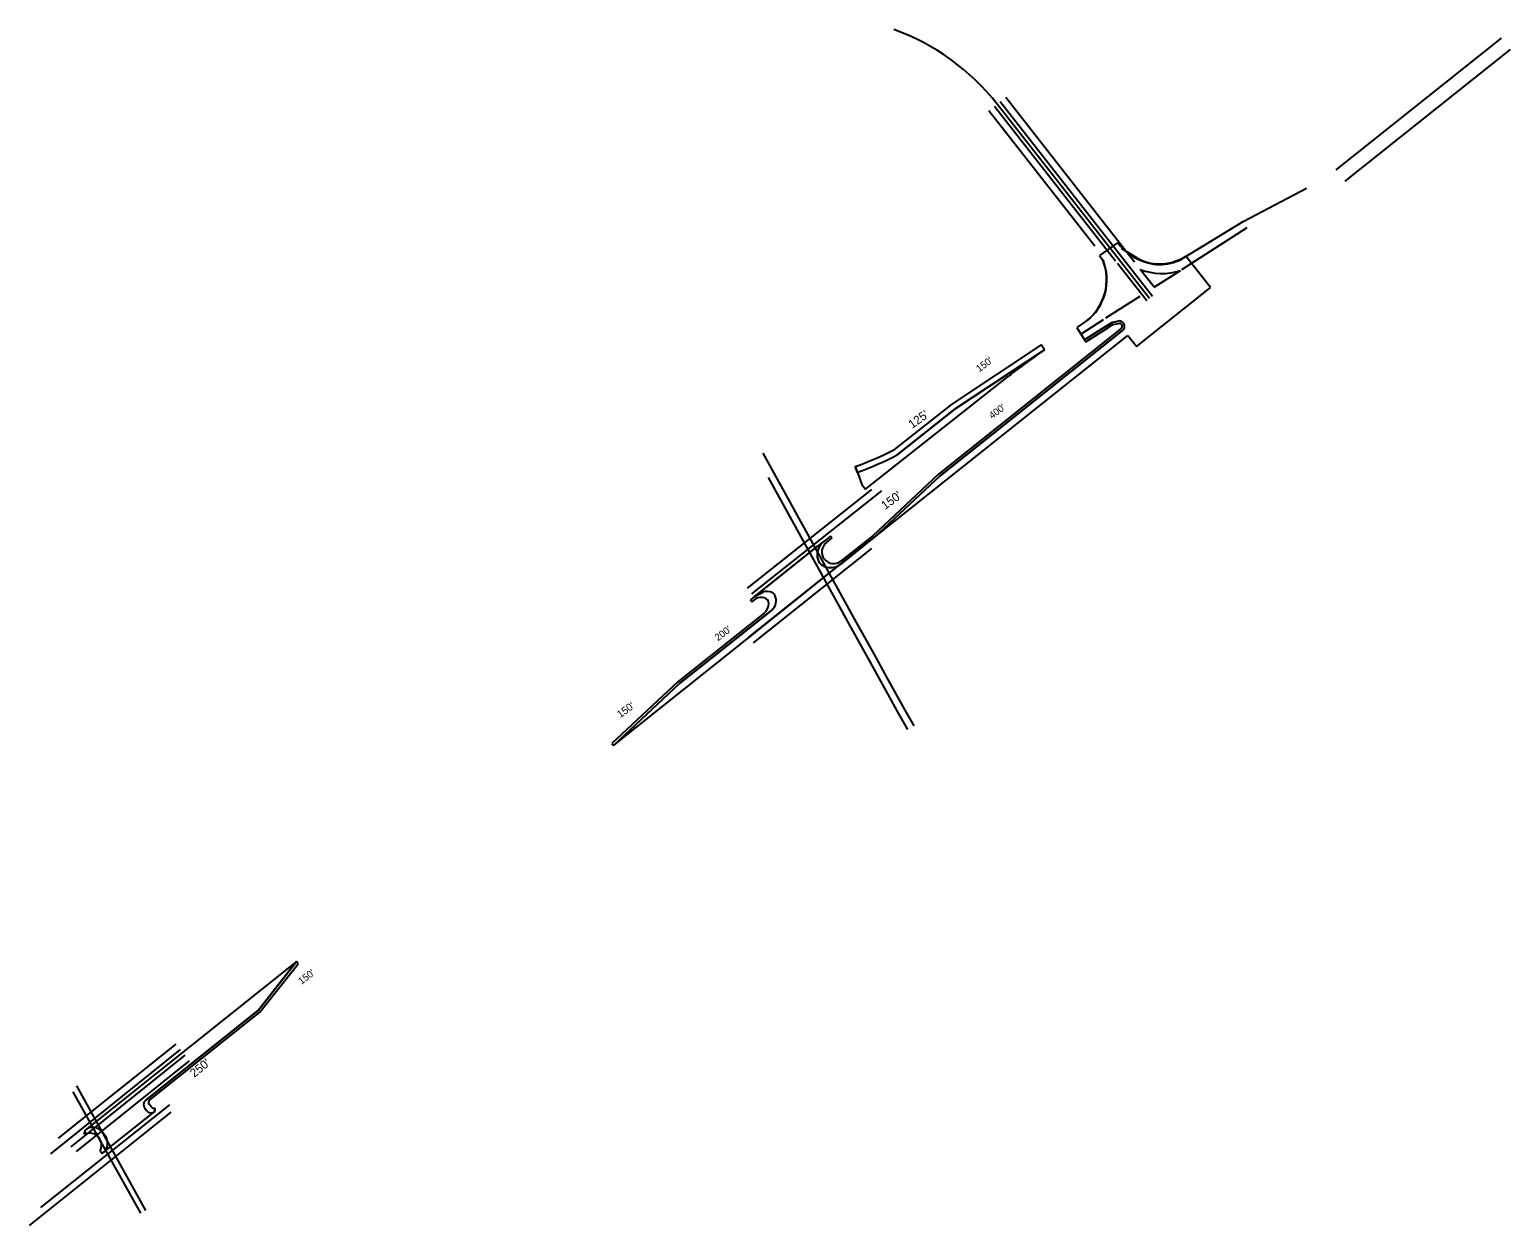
# Model space of a CAD drawing. Extents: x -200 to 1730068, y -325 to 756043.
# Drawn here: x 1666133 to 1668598, y 754052 to 756043 of the extents above; entities that cross this region are included whole.
import ezdxf

# ---------------------------------------------------------------- set-up
doc = ezdxf.new("R2010")
doc.units = 0
for name, color, linetype in [('DESIGN - SCRATCH - User 1', 7, 'Continuous'), ('DESIGN - SCRATCH - User 4', 7, 'Continuous'), ('DESIGN - SCRATCH - User 5', 7, 'Continuous'), ('DESIGN - SCRATCH - User 6', 7, 'Continuous')]:
    doc.layers.add(name, color=color, linetype=linetype)

msp = doc.modelspace()

# ---------------------------------------------------------------- linework, layer by layer
at = {"layer": 'DESIGN - SCRATCH - User 1'}
for p, q in [((1667328.2, 755112.8), (1667535.3, 755277.3)), ((1667335.6, 755103.4), (1667551.9, 755275.2)), ((1667526.8, 755188.3), (1667330.1, 755031.4)), ((1667534.3, 755178.9), (1667337.6, 755022)), ((1666383.9, 754344.5), (1666168, 754171.2)), ((1666376.4, 754353.9), (1666180.8, 754196.9)), ((1666391.4, 754335.1), (1666201.6, 754182.8)), ((1666398.9, 754325.8), (1666210.9, 754174.9)), ((1666366, 754252.9), (1666151.6, 754081.8)), ((1666133.2, 754051.9), (1666368.6, 754240.3))]:
    msp.add_line(p, q, dxfattribs=at)
for points in [[(1667353.8, 755337.9), (1667508.6, 755057.1), (1667538.8, 755002.5), (1667559.7, 754964.9), (1667590.2, 754909.6), (1667604.8, 754883.5)], [(1667362.4, 755297.4), (1667498.1, 755051.3), (1667528.3, 754996.6), (1667549.2, 754959.1), (1667579.7, 754903.8), (1667594.3, 754877.7)], [(1666318.1, 754072), (1666205.8, 754274.4)], [(1666326.8, 754076.9), (1666211.8, 754284.2)]]:
    msp.add_lwpolyline(points, dxfattribs=at)
at = {"layer": 'DESIGN - SCRATCH - User 5'}
for p, q in [((1668308.2, 755809.7), (1668583, 756028.8)), ((1668323.2, 755790.9), (1668598, 756010.1)), ((1668002.1, 755598.7), (1667748.6, 755922.5)), ((1667972.6, 755655.9), (1667758, 755929.9)), ((1667906.3, 755682.2), (1667729.7, 755907.7)), ((1667940.7, 755657.6), (1667739.1, 755915.1)), ((1667997.4, 755595), (1667743.8, 755918.8)), ((1668153.3, 755723.7), (1668258.9, 755778.7)), ((1668055.2, 755663.3), (1668153.3, 755723.7)), ((1668051.1, 755643.5), (1668160, 755713.2)), ((1667980.5, 755660.2), (1667950.7, 755678.4)), ((1667992.7, 755591.3), (1667944, 755653.5)), ((1668005.2, 755614.2), (1667982, 755643.8)), ((1668005.2, 755614.2), (1668048.7, 755642)), ((1667924.8, 755562.8), (1667981.7, 755599.2)), ((1667883.1, 755536.1), (1667921, 755560.3))]:
    msp.add_line(p, q, dxfattribs=at)
for centre, radius, start, end in [((1667443.1, 755683.3), 382, 38.0588, 70.3385), ((1667838.9, 755626.6), 87.5, 307.7838, 22.0237), ((1668015, 755727.9), 76.1, 243.0435, 301.8773), ((1668017.8, 755733.3), 96.4, 248.2126, 288.6594)]:
    msp.add_arc(centre, radius, start, end, dxfattribs=at)
at = {"layer": 'DESIGN - SCRATCH - User 6'}
for p, q in [((1667944.2, 755688.2), (1667914.1, 755667)), ((1667914.1, 755667), (1667919.6, 755659.2)), ((1668099, 755613.6), (1668057.7, 755665.5)), ((1667983.2, 755521.2), (1668090, 755606.4)), ((1667892.2, 755557.8), (1667876.2, 755546.8)), ((1667918, 755544.8), (1667935, 755555.4)), ((1667935, 755555.4), (1667918, 755544.8)), ((1667920.1, 755541.4), (1667936.5, 755551.7)), ((1667935, 755555.4), (1667945.6, 755557.7)), ((1667945.6, 755557.7), (1667935, 755555.4)), ((1667936.5, 755551.7), (1667946.4, 755553.8)), ((1667950.6, 755552), (1667951.4, 755550.8)), ((1667954, 755554.1), (1667954.8, 755552.9)), ((1667954.8, 755552.9), (1667954, 755554.1)), ((1667539.2, 755197.1), (1667961.5, 755533.9)), ((1667950.5, 755545.6), (1667646.3, 755303)), ((1667953, 755542.4), (1667648.9, 755300)), ((1667648.9, 755300), (1667953, 755542.4)), ((1667876.2, 755546.8), (1667889.2, 755526.6)), ((1667889.2, 755526.6), (1667918, 755544.8)), ((1667918, 755544.8), (1667889.2, 755526.6)), ((1667889.2, 755526.6), (1667891.4, 755523)), ((1667891.4, 755523), (1667889.2, 755526.6)), ((1667891.4, 755523), (1667920.1, 755541.4)), ((1667961.5, 755533.9), (1667976.1, 755515.6)), ((1667817, 755518.3), (1667668.1, 755419.4)), ((1667822.5, 755510), (1667674, 755411.3)), ((1667674, 755411.3), (1667822.5, 755510)), ((1667822.5, 755510), (1667817, 755518.3)), ((1667822.5, 755510), (1667817, 755518.3)), ((1667524.7, 755278), (1667762, 755465.6)), ((1667674, 755411.3), (1667577.2, 755334.8)), ((1667577.2, 755334.8), (1667674, 755411.3)), ((1667507.6, 755315.3), (1667511, 755305.8)), ((1667511, 755305.8), (1667507.6, 755315.3)), ((1667511, 755305.8), (1667518.6, 755285.8)), ((1667518.6, 755285.8), (1667524.7, 755278)), ((1667646.3, 755303), (1667536.6, 755200.1)), ((1667648.9, 755300), (1667539.2, 755197.1)), ((1667539.2, 755197.1), (1667648.9, 755300)), ((1667444.9, 755182.6), (1667339.4, 755098.7)), ((1667339.4, 755098.7), (1667444.9, 755182.6)), ((1667444.9, 755182.6), (1667441.3, 755179.4)), ((1667454.1, 755189.9), (1667444.9, 755182.6)), ((1667466.4, 755199.7), (1667455.1, 755190.7)), ((1667459.4, 755189), (1667468.9, 755196.6)), ((1667468.9, 755196.6), (1667466.4, 755199.7)), ((1667468.9, 755196.6), (1667466.4, 755199.7)), ((1667536.6, 755200.1), (1667483.9, 755158.3)), ((1667484.5, 755153.7), (1667539.2, 755197.1)), ((1667379, 755069.4), (1667483.1, 755152.7)), ((1667339.4, 755098.7), (1667333.1, 755093.7)), ((1667333.1, 755093.7), (1667335.8, 755090.3)), ((1667335.8, 755090.3), (1667333.1, 755093.7)), ((1667335.8, 755090.3), (1667342.3, 755095.3)), ((1667339.4, 755098.7), (1667354.6, 755106.7)), ((1667354.6, 755106.7), (1667339.4, 755098.7)), ((1667356, 755071.5), (1667212.4, 754957.1)), ((1667368.5, 755076.4), (1667215.1, 754954)), ((1667215.1, 754954), (1667368.5, 755076.4)), ((1667222.6, 754944.7), (1667379, 755069.4)), ((1667212.4, 754957.1), (1667102.4, 754854.2)), ((1667215.1, 754954), (1667105.4, 754850.9)), ((1667105.4, 754850.9), (1667215.1, 754954)), ((1667105.4, 754850.9), (1667222.6, 754944.7)), ((1667102.4, 754854.2), (1667105.4, 754850.9)), ((1667102.4, 754854.2), (1667105.4, 754850.9)), ((1666577.3, 754491.5), (1666225.7, 754210.6)), ((1666514.1, 754410.3), (1666577.3, 754491.5)), ((1666577.3, 754491.5), (1666514.1, 754410.3)), ((1666580.4, 754487.6), (1666577.3, 754491.5)), ((1666580.4, 754487.6), (1666577.3, 754491.5)), ((1666516.6, 754407.2), (1666580.4, 754487.6)), ((1666326.6, 754260.5), (1666514.1, 754410.3)), ((1666514.1, 754410.3), (1666326.6, 754260.5)), ((1666333, 754260.5), (1666516.6, 754407.2)), ((1666327.6, 754243.2), (1666325, 754246.5)), ((1666325, 754246.5), (1666327.6, 754243.2)), ((1666336.1, 754248.6), (1666332.2, 754253.5)), ((1666341.7, 754241.6), (1666341.8, 754247.1)), ((1666341.8, 754247.1), (1666341.7, 754241.6)), ((1666255.7, 754173), (1666341.7, 754241.6)), ((1666225.7, 754210.6), (1666224.3, 754203.7)), ((1666224.3, 754203.7), (1666225.7, 754210.6)), ((1666248.4, 754198.1), (1666248.5, 754198)), ((1666253.8, 754207.5), (1666258.9, 754201.1)), ((1666258.9, 754201.1), (1666253.8, 754207.5)), ((1666250.6, 754176.2), (1666254.1, 754171.7)), ((1666250.6, 754176.2), (1666254.1, 754171.7)), ((1666254.1, 754171.7), (1666255.7, 754173))]:
    msp.add_line(p, q, dxfattribs=at)
for points in [[(1667976.1, 755515.6), (1667983.2, 755521.2), (1668090, 755606.4), (1668099, 755613.6)], [(1667668.1, 755419.4), (1667571.8, 755343.2), (1667571.7, 755343.2)], [(1667571.7, 755343.2), (1667571.7, 755343.2)]]:
    msp.add_lwpolyline(points, dxfattribs=at)
for centre, radius, start, end in [((1668013.2, 755737.9), 85, 215.7352, 301.6076), ((1667838.9, 755626.6), 87, 307.7838, 22.0237), ((1668015, 755727.9), 75.6, 243.0435, 301.8773), ((1667947.2, 755549.9), 8, 32.0387, 102.017), ((1667947.2, 755549.9), 8, 32.0387, 102.017), ((1667947.2, 755549.9), 4, 32.0387, 102.017), ((1667948, 755548.7), 8, 308.5692, 32.0387), ((1667948, 755548.7), 8, 308.5692, 32.0387), ((1667948, 755548.7), 4, 308.5692, 32.0387), ((1669705.7, 752877.5), 3236.7, 125.5782, 126.9072), ((1667322.4, 755827.3), 544.5, 289.8852, 297.2499), ((1667322.4, 755827.3), 554.5, 289.8852, 297.3546), ((1667322.4, 755827.3), 554.5, 289.8852, 297.3546), ((1667473.9, 755167.3), 30, 128.6002, 178.8957), ((1667473.9, 755167.3), 30, 131.1429, 178.8957), ((1667471.9, 755173.4), 20, 128.6002, 216.2117), ((1667463.9, 755167.5), 20, 178.8957, 258.4311), ((1667463.9, 755167.5), 20, 178.8957, 258.4311), ((1667463.8, 755167.5), 10, 216.2117, 220.7157), ((1667471.4, 755174), 20, 220.7157, 308.4124), ((1667465.9, 755177.3), 30, 258.4311, 305.1493), ((1667465.9, 755177.3), 30, 258.4311, 305.1493), ((1667465.9, 755177.3), 30, 305.1493, 308.4124), ((1667360.7, 755086), 21.5, 68.7595, 106.3976), ((1667360.7, 755086), 21.5, 68.7595, 106.3976), ((1667351.2, 755077.5), 20, 76.7907, 116.5179), ((1667353.5, 755087.2), 10, 0.3476, 76.7907), ((1667343.5, 755087.1), 20, 308.5692, 0.3476), ((1667364.9, 755096.7), 10, 28.1729, 68.7595), ((1667364.9, 755096.7), 10, 28.1729, 68.7595), ((1667356, 755092), 20, 308.5692, 28.1729), ((1667356, 755092), 20, 308.5692, 28.1729), ((1666332.8, 754252.7), 10, 128.6155, 218.5766), ((1666332.8, 754252.7), 10, 128.6155, 218.5766), ((1666336.1, 754256.6), 5, 128.6155, 218.5766), ((1666340, 754251.8), 5, 218.5766, 291.7284), ((1666335.4, 754249.4), 10, 218.5766, 308.5766), ((1666335.4, 754249.4), 10, 218.5766, 308.5766), ((1666232.8, 754185.6), 20, 38.5766, 115.2534), ((1666238.1, 754195), 20, 38.5766, 128.6155), ((1666238.1, 754195), 20, 38.5766, 128.6155), ((1666232.9, 754185.5), 20, 332.0654, 38.5766), ((1666243.2, 754188.6), 20, 308.5766, 38.5766), ((1666243.2, 754188.6), 20, 308.5766, 38.5766)]:
    msp.add_arc(centre, radius, start, end, dxfattribs=at)

# ---------------------------------------------------------------- texts
at = {"layer": 'DESIGN - SCRATCH - User 4'}
for s, height, rotation, p in [("150'", 11.72, 36.8801, (1667714.1, 755472.2)), ("125'", 14.35, 36.1522, (1667602.4, 755377.9)), ("400'", 11.72, 36.8801, (1667735.4, 755394)), ("150'", 14.35, 36.1522, (1667557.2, 755243)), ("200'", 11.72, 36.8801, (1667279, 755024.3)), ("150'", 12.38, 36.1522, (1667116.5, 754896.2)), ("150'", 11.72, 36.8801, (1666585.7, 754452.4)), ("250'", 14.35, 38.6793, (1666407.2, 754297.4))]:
    msp.add_text(s, height=height, rotation=rotation, dxfattribs=at).set_placement(p)

doc.saveas('drawing.dxf')
